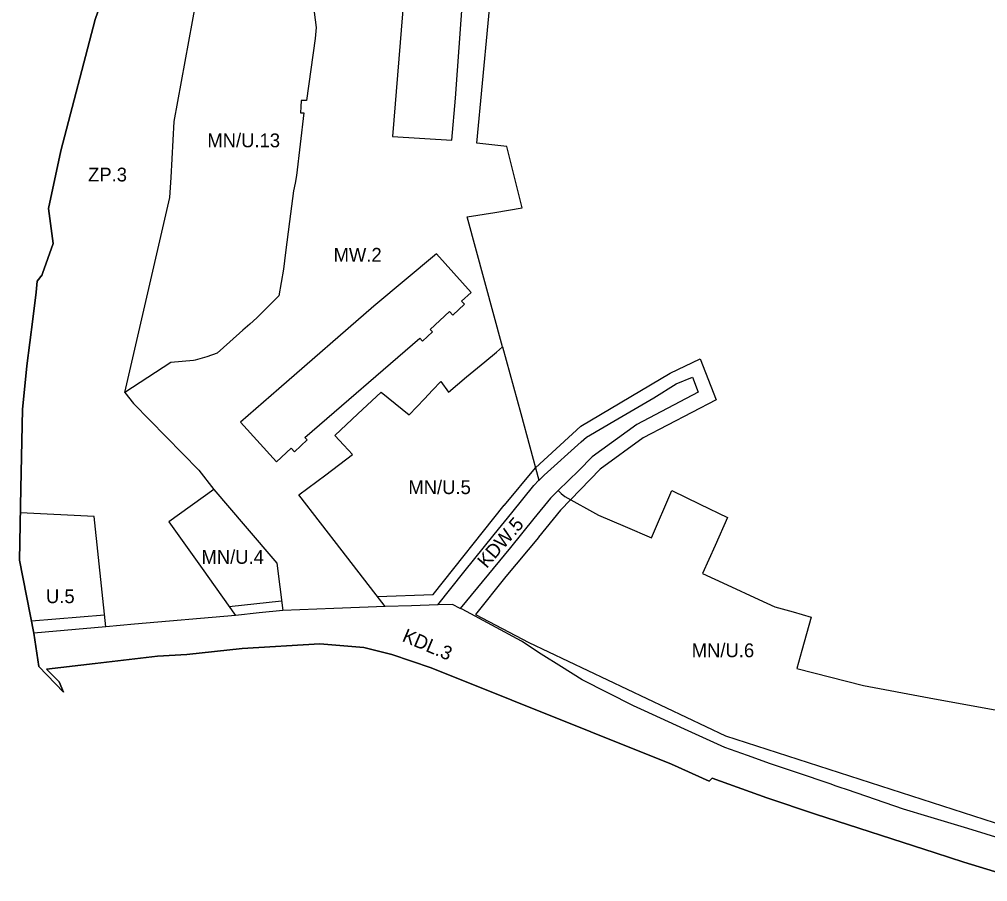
# Model space of a CAD drawing. Extents: x 7423274 to 7424514, y 5542390 to 5544261.
# Drawn here: x 7423604.9 to 7423885.8, y 5543359.2 to 5543609.4 of the extents above; entities that cross this region are included whole.
import ezdxf

# ---------------------------------------------------------------- set-up
doc = ezdxf.new("R2010")
doc.units = 0
for name, color, linetype in [('granica obszaru objętego planem', 7, 'Continuous'), ('LIN_Granica Planu', 7, 'Continuous'), ('linie rozgraniczające tereny o różnym przeznaczeniu lub różnych zasadach zagospodarowania', 7, 'Continuous'), ('nieprzekraczalna linia zabudowy', 7, 'Continuous'), ('oznaczenia terenów', 7, 'Continuous')]:
    doc.layers.add(name, color=color, linetype=linetype)

msp = doc.modelspace()

# ---------------------------------------------------------------- linework, layer by layer
at = {"layer": 'granica obszaru objętego planem'}
for p, q in [((7423610.12, 5543533.37), (7423611.52, 5543535.27)), ((7423611.52, 5543535.27), (7423611.66, 5543535.65)), ((7423609.74, 5543530.21), (7423610.12, 5543533.37)), ((7423609.08, 5543431.24), (7423604.91, 5543452.42)), ((7423712.97, 5543425.06), (7423704.84, 5543427.08)), ((7423644.95, 5543424.62), (7423626.89, 5543422.49)), ((7423653.48, 5543425.08), (7423644.95, 5543424.62)), ((7423669.52, 5543426.81), (7423653.48, 5543425.08)), ((7423626.89, 5543422.49), (7423612.74, 5543420.83)), ((7423612.74, 5543420.83), (7423616.46, 5543417.18)), ((7423616.46, 5543417.18), (7423617.69, 5543414.18)), ((7423805.02, 5543388.36), (7423794.06, 5543393.25)), ((7423870.6, 5543367.48), (7423835.85, 5543378.76)), ((7423878.95, 5543364.84), (7423870.6, 5543367.48)), ((7423897.3, 5543359.16), (7423878.95, 5543364.84))]:
    msp.add_line(p, q, dxfattribs=at)
for points in [[(7423616.9, 5543571.25), (7423626.88, 5543609.36), (7423641.37, 5543650.9)], [(7423611.66, 5543535.65), (7423614.76, 5543544.38), (7423613.34, 5543554.46), (7423616.9, 5543571.25)], [(7423607.04, 5543508.87), (7423608.82, 5543522.36), (7423609.74, 5543530.21)], [(7423604.91, 5543452.42), (7423605.38, 5543473.26), (7423605.79, 5543496.19), (7423607.04, 5543508.87)], [(7423617.69, 5543414.18), (7423610.57, 5543421.58), (7423609.08, 5543431.24)], [(7423704.84, 5543427.08), (7423692.08, 5543428.13), (7423669.52, 5543426.81)], [(7423794.06, 5543393.25), (7423724.39, 5543421.16), (7423712.97, 5543425.06)], [(7423835.85, 5543378.76), (7423821.8, 5543383.47), (7423805.87, 5543389.22), (7423805.02, 5543388.36)]]:
    msp.add_lwpolyline(points, dxfattribs=at)
at = {"layer": 'LIN_Granica Planu'}
for p, q in [((7423611.52, 5543535.27), (7423610.12, 5543533.37)), ((7423611.66, 5543535.65), (7423611.52, 5543535.27)), ((7423610.12, 5543533.37), (7423609.74, 5543530.21)), ((7423604.91, 5543452.42), (7423609.08, 5543431.24)), ((7423704.84, 5543427.08), (7423712.97, 5543425.06)), ((7423626.89, 5543422.49), (7423644.95, 5543424.62)), ((7423644.95, 5543424.62), (7423653.48, 5543425.08)), ((7423653.48, 5543425.08), (7423669.52, 5543426.81)), ((7423612.74, 5543420.83), (7423626.89, 5543422.49)), ((7423616.46, 5543417.18), (7423612.74, 5543420.83)), ((7423617.69, 5543414.18), (7423616.46, 5543417.18)), ((7423794.06, 5543393.25), (7423805.02, 5543388.36)), ((7423835.85, 5543378.76), (7423870.6, 5543367.48)), ((7423870.6, 5543367.48), (7423878.95, 5543364.84)), ((7423878.95, 5543364.84), (7423897.3, 5543359.16))]:
    msp.add_line(p, q, dxfattribs=at)
for points in [[(7423641.37, 5543650.9), (7423626.88, 5543609.36), (7423616.9, 5543571.25)], [(7423616.9, 5543571.25), (7423613.34, 5543554.46), (7423614.76, 5543544.38), (7423611.66, 5543535.65)], [(7423609.74, 5543530.21), (7423608.82, 5543522.36), (7423607.04, 5543508.87)], [(7423607.04, 5543508.87), (7423605.79, 5543496.19), (7423605.38, 5543473.26), (7423604.91, 5543452.42)], [(7423609.08, 5543431.24), (7423610.57, 5543421.58), (7423617.69, 5543414.18)], [(7423669.52, 5543426.81), (7423692.08, 5543428.13), (7423704.84, 5543427.08)], [(7423712.97, 5543425.06), (7423724.39, 5543421.16), (7423794.06, 5543393.25)], [(7423805.02, 5543388.36), (7423805.87, 5543389.22), (7423821.8, 5543383.47), (7423835.85, 5543378.76)]]:
    msp.add_lwpolyline(points, dxfattribs=at)
at = {"layer": 'linie rozgraniczające tereny o różnym przeznaczeniu lub różnych zasadach zagospodarowania'}
for p, q in [((7423762.08, 5543471.79), (7423761.2, 5543472.62)), ((7423762.1, 5543471.78), (7423762.08, 5543471.79))]:
    msp.add_line(p, q, dxfattribs=at)
for points in [[(7423605.22, 5543466.15), (7423605.38, 5543473.26), (7423605.79, 5543496.19), (7423607.04, 5543508.87), (7423608.82, 5543522.36), (7423609.74, 5543530.21), (7423610.12, 5543533.37), (7423611.52, 5543535.27), (7423611.66, 5543535.65), (7423614.76, 5543544.38), (7423613.34, 5543554.46), (7423616.9, 5543571.25), (7423626.88, 5543609.36), (7423641.37, 5543650.9)], [(7423635.49, 5543501.06), (7423648.59, 5543557.72), (7423648.91, 5543563.5), (7423649.79, 5543579.73), (7423656.24, 5543614.61), (7423662.69, 5543649.48)], [(7423745.12, 5543514.34), (7423739.99, 5543533.2), (7423734.85, 5543552.05), (7423742.81, 5543553.35), (7423750.78, 5543554.65), (7423748.56, 5543563.58), (7423746.35, 5543572.52), (7423741.99, 5543572.99), (7423737.63, 5543573.46), (7423740.9, 5543608.25), (7423744.17, 5543643.05)], [(7423690.48, 5543611.43), (7423690.76, 5543609.24), (7423691.05, 5543607.05), (7423690.68, 5543603.83), (7423689.44, 5543594.85), (7423688.21, 5543585.87), (7423686.71, 5543585.81), (7423686.58, 5543584.02), (7423686.46, 5543582.24), (7423687.46, 5543582.28), (7423686.38, 5543573.18), (7423685.29, 5543564.08), (7423684.88, 5543561.86), (7423684.47, 5543559.65), (7423683.32, 5543550.69), (7423682.16, 5543541.73), (7423681.54, 5543536.93), (7423680.87, 5543533.04), (7423680.2, 5543529.15), (7423677.01, 5543525.96), (7423673.81, 5543522.77), (7423671.78, 5543520.96), (7423669.75, 5543519.16), (7423666.01, 5543515.82), (7423662.27, 5543512.49), (7423659.29, 5543511.49), (7423655.88, 5543510.45), (7423655.46, 5543510.41), (7423652.14, 5543510.09), (7423648.82, 5543509.78), (7423642.16, 5543505.42), (7423635.49, 5543501.06)], [(7423711.04, 5543438.98), (7423698.52, 5543455.18), (7423686, 5543471.39), (7423693.79, 5543477.23), (7423701.59, 5543483.08), (7423699.02, 5543485.84), (7423696.44, 5543488.6), (7423703.14, 5543494.88), (7423709.84, 5543501.15), (7423713.94, 5543497.88), (7423718.03, 5543494.61), (7423720.24, 5543496.96), (7423722.44, 5543499.31), (7423724.79, 5543501.82), (7423727.15, 5543504.34), (7423729.38, 5543501.21), (7423734.66, 5543505.61), (7423739.94, 5543510.01), (7423743.32, 5543512.82), (7423745.12, 5543514.34)], [(7423745.12, 5543514.34), (7423750.39, 5543494.99), (7423755.66, 5543475.64)], [(7423755.67, 5543475.65), (7423757.12, 5543477.15), (7423767.86, 5543486.74), (7423769.46, 5543488.1), (7423778.55, 5543493.43), (7423788.95, 5543499.53), (7423795.51, 5543503.58), (7423800.19, 5543505.57), (7423801.87, 5543501.23), (7423801.88, 5543501.2), (7423784.05, 5543491.81), (7423771.12, 5543482.47), (7423767.19, 5543478.49), (7423761.2, 5543472.62)], [(7423635.49, 5543501.06), (7423637.99, 5543497.9), (7423647.48, 5543488.22), (7423656.98, 5543478.54), (7423661.3, 5543473)], [(7423771.12, 5543482.47), (7423771.12, 5543482.47)], [(7423726.29, 5543439.44), (7423733.86, 5543448.92), (7423742.7, 5543459.88), (7423747.78, 5543466.22), (7423754.17, 5543474.11), (7423755.65, 5543475.63), (7423755.66, 5543475.64)], [(7423755.66, 5543475.64), (7423755.67, 5543475.65)], [(7423661.3, 5543473), (7423648.28, 5543463.54), (7423657.96, 5543449.99), (7423667.63, 5543436.43)], [(7423661.3, 5543473), (7423670.46, 5543462.29), (7423679.62, 5543451.58), (7423681.31, 5543437.82)], [(7423761.2, 5543472.62), (7423759.01, 5543470.47), (7423754.14, 5543464.56), (7423747.42, 5543456.14), (7423732.84, 5543438.45)], [(7423762.1, 5543471.78), (7423763.2, 5543470.95), (7423772.9, 5543465.5), (7423780.62, 5543462.22), (7423788.34, 5543458.94), (7423794.18, 5543472.69), (7423802.28, 5543468.74), (7423810.38, 5543464.78), (7423806.73, 5543456.67), (7423803.07, 5543448.57), (7423810.25, 5543445.33), (7423819.48, 5543441.05), (7423824.09, 5543438.92), (7423829.37, 5543437.42), (7423834.65, 5543435.93), (7423831.92, 5543426.28), (7423830.43, 5543420.98), (7423849.77, 5543416.04), (7423868.85, 5543412.52), (7423892.72, 5543408.15), (7423902.32, 5543406.39)], [(7423609.08, 5543431.24), (7423604.91, 5543452.42), (7423605.22, 5543466.15)], [(7423629.97, 5543433.09), (7423626.61, 5543465.16), (7423605.22, 5543466.15)], [(7423711.04, 5543438.98), (7423696.17, 5543438.4), (7423681.31, 5543437.82)], [(7423726.29, 5543439.44), (7423718.67, 5543439.21), (7423711.04, 5543438.98)], [(7423732.84, 5543438.45), (7423730.59, 5543439.56), (7423726.29, 5543439.44)], [(7423890.76, 5543371.25), (7423880.07, 5543374.56), (7423868.52, 5543378.02), (7423861.46, 5543380.18), (7423853.3, 5543382.99), (7423845.15, 5543385.79), (7423842.78, 5543386.6), (7423841.6, 5543387), (7423840.42, 5543387.41), (7423839.6, 5543387.69), (7423831.21, 5543390.54), (7423822.83, 5543393.39), (7423816.2, 5543395.74), (7423809.57, 5543398.09), (7423797.92, 5543403.39), (7423786.27, 5543408.69), (7423783.11, 5543410.13), (7423775.66, 5543413.91), (7423768.21, 5543417.69), (7423762.24, 5543421.45), (7423756.26, 5543425.2), (7423750.6, 5543428.97), (7423741.96, 5543433.61), (7423733.34, 5543438.21), (7423732.84, 5543438.45)], [(7423667.63, 5543436.43), (7423638.36, 5543433.83), (7423629.97, 5543433.09)], [(7423681.31, 5543437.82), (7423674.47, 5543437.12), (7423667.63, 5543436.43)], [(7423629.97, 5543433.09), (7423609.08, 5543431.24)], [(7423897.3, 5543359.16), (7423878.95, 5543364.84), (7423870.6, 5543367.48), (7423835.85, 5543378.76), (7423821.8, 5543383.47), (7423805.87, 5543389.22), (7423805.02, 5543388.36), (7423794.06, 5543393.25), (7423724.39, 5543421.16), (7423712.97, 5543425.06), (7423704.84, 5543427.08), (7423692.08, 5543428.13), (7423669.52, 5543426.81), (7423653.48, 5543425.08), (7423644.95, 5543424.62), (7423626.89, 5543422.49), (7423612.74, 5543420.83), (7423616.46, 5543417.18), (7423617.69, 5543414.18), (7423610.57, 5543421.58), (7423609.08, 5543431.23), (7423609.08, 5543431.24)]]:
    msp.add_lwpolyline(points, dxfattribs=at)
at = {"layer": 'nieprzekraczalna linia zabudowy'}
for p, q in [((7423716.94, 5543621.63), (7423713.15, 5543575.42)), ((7423713.15, 5543575.42), (7423730.35, 5543574.31)), ((7423735.96, 5543530.14), (7423725.96, 5543541.35)), ((7423733.2, 5543527.64), (7423735.96, 5543530.14)), ((7423687.7, 5543488.04), (7423721.14, 5543516.83)), ((7423669.05, 5543492.48), (7423679.53, 5543481)), ((7423708.77, 5543441.91), (7423725.01, 5543442.52)), ((7423665.8, 5543438.99), (7423680.96, 5543440.66)), ((7423608.39, 5543434.84), (7423629.62, 5543436.59))]:
    msp.add_line(p, q, dxfattribs=at)
for points in [[(7423730.35, 5543574.31), (7423731.42, 5543586.5), (7423734.16, 5543624.08)], [(7423725.96, 5543541.35), (7423707.78, 5543526.14), (7423680.21, 5543502.18), (7423669.05, 5543492.48)], [(7423729.68, 5543524.65), (7423730.69, 5543523.58), (7423734.05, 5543526.75), (7423733.2, 5543527.64)], [(7423721.14, 5543516.83), (7423721.9, 5543516.03), (7423724.75, 5543518.71), (7423724.1, 5543519.4), (7423729.68, 5543524.65)], [(7423793.67, 5543506.66), (7423793.69, 5543506.67), (7423802.43, 5543510.87), (7423807.05, 5543498.93)], [(7423745.61, 5543468.43), (7423754.67, 5543479.28), (7423767.77, 5543491.37), (7423793.69, 5543506.67)], [(7423807.05, 5543498.93), (7423785.91, 5543487.98), (7423773.45, 5543478.86), (7423761.86, 5543466.94), (7423755.56, 5543459.09)], [(7423679.53, 5543481), (7423683.74, 5543484.94), (7423684.74, 5543483.88), (7423688.41, 5543487.32), (7423687.7, 5543488.04)], [(7423725.01, 5543442.52), (7423745.58, 5543468.39)], [(7423745.58, 5543468.39), (7423745.61, 5543468.43)], [(7423755.53, 5543459.06), (7423746.02, 5543447.67), (7423737.24, 5543436.72)], [(7423755.56, 5543459.09), (7423755.53, 5543459.06)], [(7423737.24, 5543436.72), (7423752.7, 5543428.57), (7423752.7, 5543428.57), (7423809.8, 5543401.5), (7423890.69, 5543375.39)]]:
    msp.add_lwpolyline(points, dxfattribs=at)

# ---------------------------------------------------------------- texts
at = {"layer": 'oznaczenia terenów'}
for s, p in [('MN/U.13', (7423659.44, 5543572.26)), ('ZP.3', (7423624.84, 5543562.34)), ('MW.2', (7423696.06, 5543539.06)), ('MN/U.5', (7423717.76, 5543471.62)), ('MN/U.4', (7423657.74, 5543451.38)), ('U.5', (7423612.63, 5543439.97)), ('MN/U.6', (7423799.96, 5543424.28))]:
    msp.add_text(s, height=4, dxfattribs=at).set_placement(p)
for s, rotation, p in [('KDW.5', 49.304, (7423740.46, 5543449.87)), ('KDL.3', 337.0785, (7423715.7, 5543429.03))]:
    msp.add_text(s, height=4, rotation=rotation, dxfattribs=at).set_placement(p)

doc.saveas('drawing.dxf')
